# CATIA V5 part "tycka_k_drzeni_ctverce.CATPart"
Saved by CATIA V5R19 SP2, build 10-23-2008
Part number: tycka_k_drzeni_ctverce
Bounding box of the stored display mesh (mm): x 0 to 300, y -8 to 8, z -8 to 8
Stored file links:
  C:\Users\Martiin\Desktop\9.semestr\Projekt-diplomka\3D model\tycka_k_drzeni_ctverce.CATPart
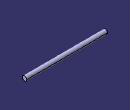
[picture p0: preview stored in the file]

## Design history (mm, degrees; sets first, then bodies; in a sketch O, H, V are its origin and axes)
Body1 (main body)
  Sketch1 on yz-plane, origin (0, 0, 0), H (0, 1, 0), V (0, 0, 1)
    circle A1 centre (0, 0) radius 8
    radius A1 = 8
  Pad1: profile Sketch1, direction (1, 0, 0), length 300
